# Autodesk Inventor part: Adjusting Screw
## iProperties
Shininess: 41.0
Length Units: 11272
Angle Units: 11279
Time Units: 11290
Mass Units: 11286
Length Display Precision: 4
Angle Display Precision: 2
Compacted: True
Company: Autodesk
Manager: Lebovitz
Created: 2000-11
Part Number: Adjusting Screw
Document SubType Name: Modeling
Designer: The PD Team
Project: Inventor Samples
Checked By: The PD Team
Density: 0.0
Volumn: 0.0
Area: 0.0
PropertySet Name: Model Information
Control State: 0
Master: False
Checked Out: False
Author: The PD Team
Revision Number: A
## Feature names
1. Extrusion1
2. Extrusion2
3. Chamfer1
4. Extrusion3
5. Extrusion4
6. Hole1
